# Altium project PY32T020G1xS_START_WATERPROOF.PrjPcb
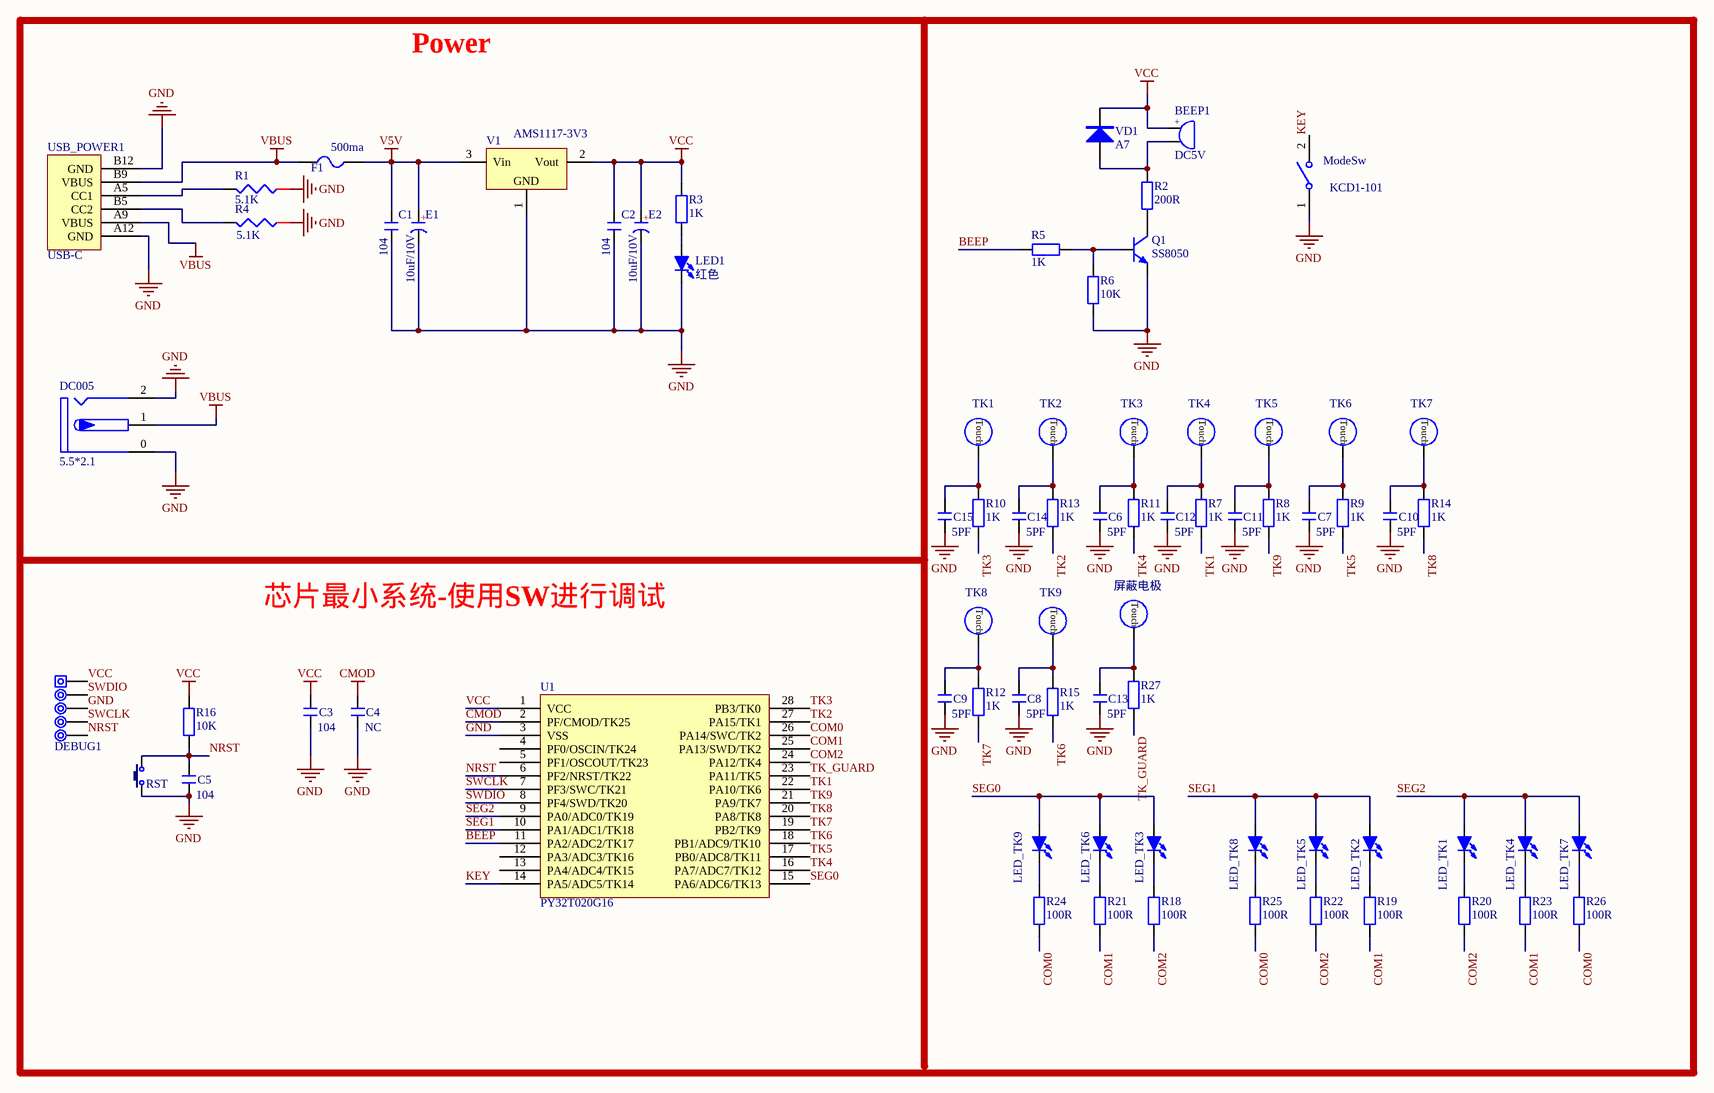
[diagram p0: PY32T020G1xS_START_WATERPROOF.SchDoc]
1 sheet, 74 parts. Net scope: global (net labels, ports and power ports of the same name join across sheets).
Board file: PY32T020G1xS_START_WATERPROOF.PcbDoc

## Sheet PY32T020G1xS_START_WATERPROOF.SchDoc
size A3

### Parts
BEEP1  DC5V  [BEEP 5x9x5.5]
C1  104  [C 0603_L]
C2  104  [C 0603_L]
C3  104  [C 0603_L]
C4  NC  [C 0603_L]
C5  104  [C 0603_L]
C6  5PF  [C 0603_L]
C7  5PF  [C 0603_L]
C8  5PF  [C 0603_L]
C9  5PF  [C 0603_L]
C10  5PF  [C 0603_L]
C11  5PF  [C 0603_L]
C12  5PF  [C 0603_L]
C13  5PF  [C 0603_L]
C14  5PF  [C 0603_L]
C15  5PF  [C 0603_L]
DC005  5.5*2.1  [DC-005P]
DEBUG1  ISP  [ISP_DIP_2.54_5P]  (value not drawn)
E1  10uF/10V  [C 0805_L]
E2  10uF/10V  [C 0805_L]
F1  500ma  [FU 0805]
LED1  红色  [LED 0805R]
LED_TK1  红色  [LED 0805R]  (value not drawn)
LED_TK2  红色  [LED 0805R]  (value not drawn)
LED_TK3  红色  [LED 0805R]  (value not drawn)
LED_TK4  红色  [LED 0805R]  (value not drawn)
LED_TK5  红色  [LED 0805R]  (value not drawn)
LED_TK6  红色  [LED 0805R]  (value not drawn)
LED_TK7  红色  [LED 0805R]  (value not drawn)
LED_TK8  红色  [LED 0805R]  (value not drawn)
LED_TK9  红色  [LED 0805R]  (value not drawn)
ModeSw  KCD1-101  [KCD1-101]
Q1  SS8050  [SOT23-3L]
R1  5.1K  [R 0603_L]
R2  200R  [R 0603_L]
R3  1K  [R 0603_L]
R4  5.1K  [R 0603_L]
R5  1K  [R 0603_L]
R6  10K  [R 0603_L]
R7  1K  [R 0603_L]
R8  1K  [R 0603_L]
R9  1K  [R 0603_L]
R10  1K  [R 0603_L]
R11  1K  [R 0603_L]
R12  1K  [R 0603_L]
R13  1K  [R 0603_L]
R14  1K  [R 0603_L]
R15  1K  [R 0603_L]
R16  10K  [R 0603_L]
R18  100R  [R 0603_L]
R19  100R  [R 0603_L]
R20  100R  [R 0603_L]
R21  100R  [R 0603_L]
R22  100R  [R 0603_L]
R23  100R  [R 0603_L]
R24  100R  [R 0603_L]
R25  100R  [R 0603_L]
R26  100R  [R 0603_L]
R27  1K  [R 0603_L]
RST  6x6x5  [TSW SMD-3*6*5]  (value not drawn)
Th_GUARD  Touch 10X10mm  [Touch-10X10mm]  (value not drawn)
TK1  Touch 10X10mm  [Touch-10X10mm]  (value not drawn)
TK2  Touch 10X10mm  [Touch-10X10mm]  (value not drawn)
TK3  Touch 10X10mm  [Touch-10X10mm]  (value not drawn)
TK4  Touch 10X10mm  [Touch-10X10mm]  (value not drawn)
TK5  Touch 10X10mm  [Touch-10X10mm]  (value not drawn)
TK6  Touch 10X10mm  [Touch-10X10mm]  (value not drawn)
TK7  Touch 10X10mm  [Touch-10X10mm]  (value not drawn)
TK8  Touch 10X10mm  [Touch-10X10mm]  (value not drawn)
TK9  Touch 10X10mm  [Touch-10X10mm]  (value not drawn)
U1  PY32T020G16  [SOP28_L]
USB_POWER1  USB-C  [USB-C/S_C]
V1  AMS1117-3V3  [SOT223_N]
VD1  A7  [SOD-123]

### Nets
CMOD: C4.2 U1.2(PF/CMOD/TK25)
GND: C1.1 C2.1 C3.1 C4.1 C5.1 C6.1 C7.1 C8.1 C9.1 C10.1 C11.1 C12.1 C13.1 C14.1 C15.1 DC005.0 DC005.2 DEBUG1.3 E1.2(K) E2.2(K) LED1.2(K) ModeSw.1 Q1.2(B) R1.1 R4.1 R6.1 RST.1 U1.3(VSS) USB_POWER1.A12(GND) USB_POWER1.B12(GND) V1.1(GND)
V5V: C1.2 E1.1(A) F1.2 V1.3(Vin)
VBUS: DC005.1 F1.1 USB_POWER1.A9(VBUS) USB_POWER1.B9(VBUS)
VCC: BEEP1.1 C2.2 C3.2 DEBUG1.1 E2.1(A) R3.2 R16.2 U1.1(VCC) V1.2(Vout) VD1.K
BEEP: R5.2 U1.11(PA2/ADC2/TK17)
COM0: R24.1 R25.1 R26.1 U1.26(PA14/SWC/TK2)
COM1: R19.1 R21.1 R23.1 U1.25(PA13/SWD/TK2)
COM2: R18.1 R20.1 R22.1 U1.24(PA12/TK4)
KEY: ModeSw.2 U1.14(PA5/ADC5/TK14)
NRST: C5.2 DEBUG1.5 R16.1 RST.2 U1.6(PF2/NRST/TK22)
SEG0: LED_TK3.1(A) LED_TK6.1(A) LED_TK9.1(A) U1.15(PA6/ADC6/TK13)
SEG1: LED_TK2.1(A) LED_TK5.1(A) LED_TK8.1(A) U1.10(PA1/ADC1/TK18)
SEG2: LED_TK1.1(A) LED_TK4.1(A) LED_TK7.1(A) U1.9(PA0/ADC0/TK19)
SWCLK: DEBUG1.4 U1.7(PF3/SWC/TK21)
SWDIO: DEBUG1.2 U1.8(PF4/SWD/TK20)
TK1: R7.1 U1.22(PA10/TK6)
TK2: R13.1 U1.27(PA15/TK1)
TK3: R10.1 U1.28(PB3/TK0)
TK4: R11.1 U1.16(PA7/ADC7/TK12)
TK5: R9.1 U1.17(PB0/ADC8/TK11)
TK6: R15.1 U1.18(PB1/ADC9/TK10)
TK7: R12.1 U1.19(PB2/TK9)
TK8: R14.1 U1.20(PA8/TK8)
TK9: R8.1 U1.21(PA9/TK7)
TK_GUARD: R27.1 U1.23(PA11/TK5)
NetBEEP1_2: BEEP1.2 R2.2 VD1.A
NetC6_2: C6.2 R11.2 TK3.Touch
NetC7_2: C7.2 R9.2 TK6.Touch
NetC8_2: C8.2 R15.2 TK9.Touch
NetC9_2: C9.2 R12.2 TK8.Touch
NetC10_2: C10.2 R14.2 TK7.Touch
NetC11_2: C11.2 R8.2 TK5.Touch
NetC12_2: C12.2 R7.2 TK4.Touch
NetC13_2: C13.2 R27.2 Th_GUARD.Touch
NetC14_2: C14.2 R13.2 TK2.Touch
NetC15_2: C15.2 R10.2 TK1.Touch
NetLED1_1: LED1.1(A) R3.1
NetLED_TK1_2: LED_TK1.2(K) R20.2
NetLED_TK2_2: LED_TK2.2(K) R19.2
NetLED_TK3_2: LED_TK3.2(K) R18.2
NetLED_TK4_2: LED_TK4.2(K) R23.2
NetLED_TK5_2: LED_TK5.2(K) R22.2
NetLED_TK6_2: LED_TK6.2(K) R21.2
NetLED_TK7_2: LED_TK7.2(K) R26.2
NetLED_TK8_2: LED_TK8.2(K) R25.2
NetLED_TK9_2: LED_TK9.2(K) R24.2
NetQ1_1: Q1.1(E) R5.1 R6.2
NetQ1_3: Q1.3(C) R2.1
NetR1_2: R1.2 USB_POWER1.A5(CC1)
NetR4_2: R4.2 USB_POWER1.B5(CC2)

Not connected (* = marked no-connect by the designer): U1 4(PF0/OSCIN/TK24) 5(PF1/OSCOUT/TK23) 12(PA3/ADC3/TK16) 13(PA4/ADC4/TK15)

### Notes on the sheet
- Power
- 芯片最小系统-使用SW进行调试
- 屏蔽电极

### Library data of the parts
BEEP1 = BEEP: 蜂鸣器; 版权归属: 源创客
C1-C15 = C: 无极性贴片电容; 版权归属: 源创客; 材质: X7R
DC005 = DC-005P: 带屏蔽DC电源接口; 版权归属: 源创客
DEBUG1 = ISP_5Pin: 程序下载端口; 版权归属: 源创客
E1 E2 = C-CM: 贴片电解电容; 版权归属: 源创客
F1 = FU: 贴片保险丝; 版权归属: 源创客
LED1 LED_TK1-LED_TK9 = LED-SMD: 贴片LED; 版权归属: 源创客
ModeSw = KCD1-101: 1路单刀船型开关; 版权归属: 源创客
Q1 = 8050-DIP: 高频放大-NPN型; 版权归属: 源创客; 属性: 40V 1.5A 1W 100MHZ
R1 R4 = R
R2 R3 R5-R16 R18-R27 = R: 贴片电阻; 版权归属: 源创客
RST = TSW DIP-2Pin-6x6: 2脚直插6x6轻触开关; BOM名称: 2脚轻触开关; 版权归属: 源创客
Th_GUARD TK1-TK9 = Touch-1P: 触控焊盘; 版权归属: 源创客
USB_POWER1 = USB-C_6P/S: USB-C_6P型母接口; BOM名称: USB-C型母接口; 版权归属: 源创客
V1 = AMS1117: 三端稳压芯片; BOM名称: 稳压芯片; 版权归属: 源创客
VD1 = DIODE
